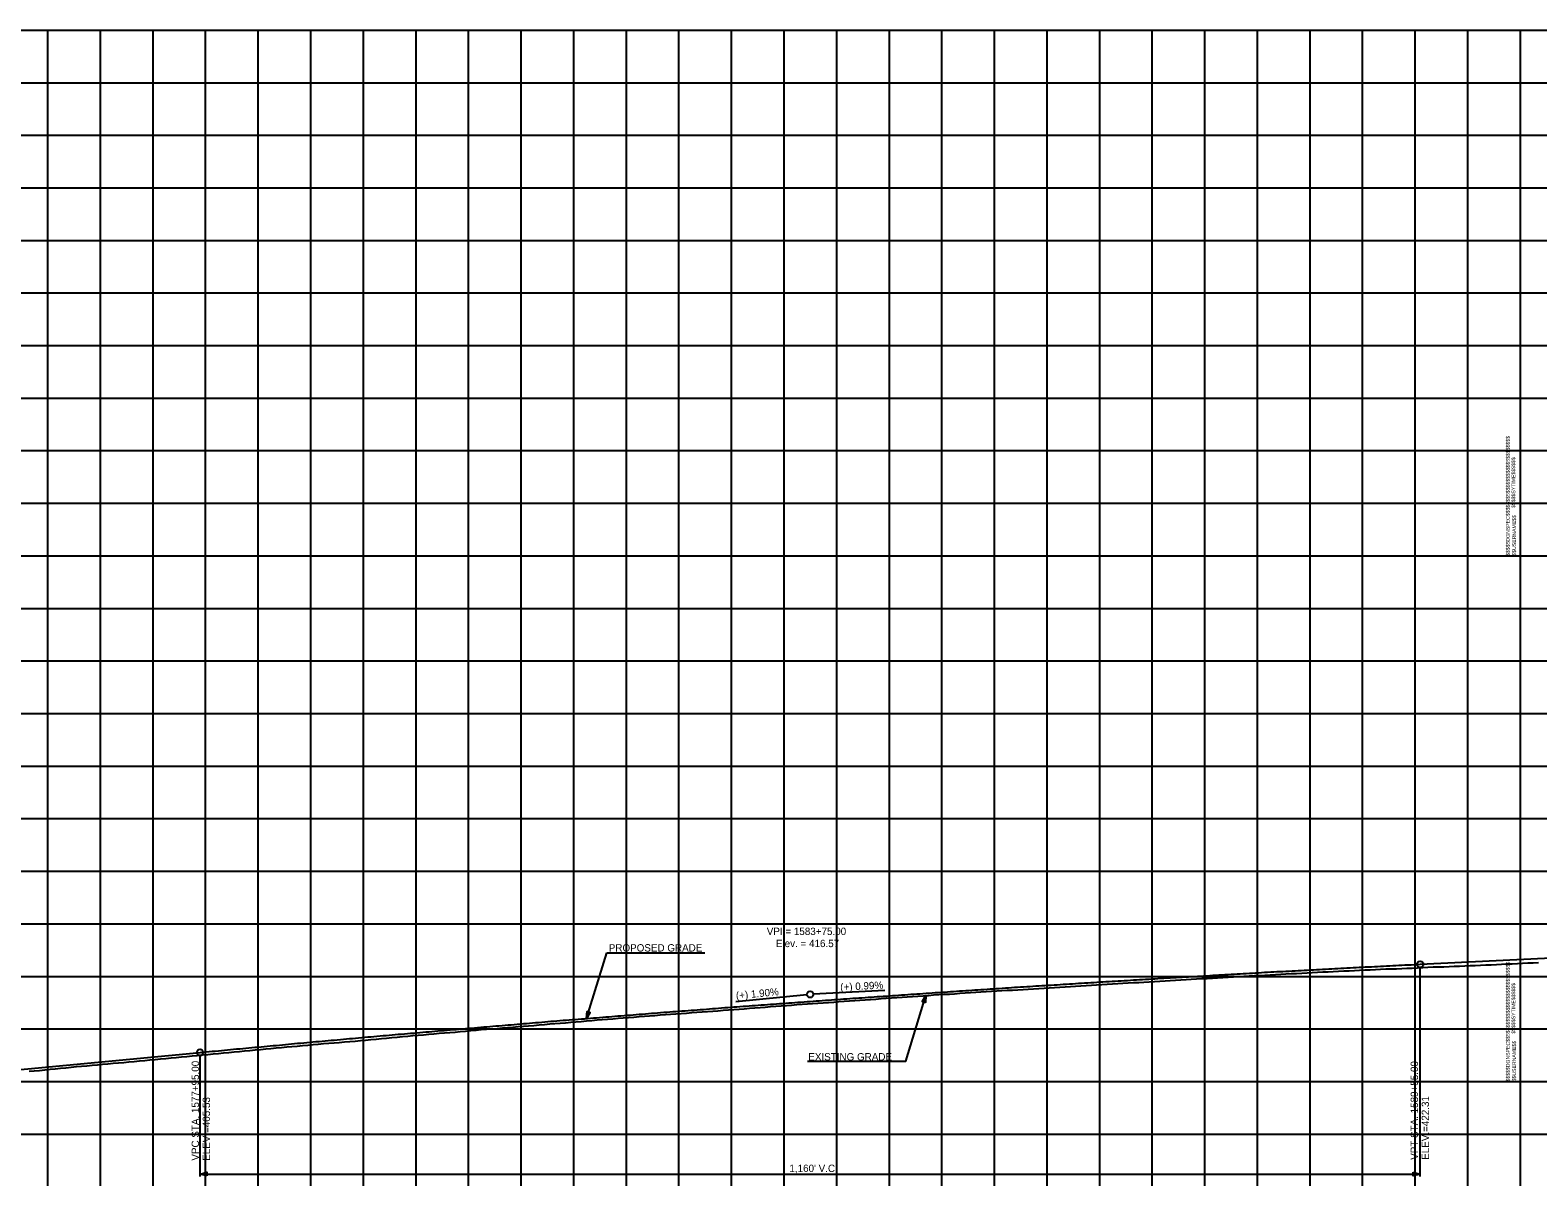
# Model space of a CAD drawing. Extents: x -90830 to 2015517, y -20856 to 836331.
# Drawn here: x 46557 to 47990, y -9888 to -8797 of the extents above; entities that cross this region are included whole.
import ezdxf

# ---------------------------------------------------------------- set-up
doc = ezdxf.new("R2010")
doc.units = 0
for name, color, linetype in [('Level 1', 7, 'Continuous'), ('RD_DDB_GradeTX', 7, 'Continuous'), ('RD_DDB_Profile_EX', 7, 'Continuous'), ('RD_DDB_Profile_Lbl', 7, 'Continuous'), ('RD_DDB_Profile_PR', 7, 'Continuous'), ('RD_DDB_StripGrade', 7, 'Continuous'), ('RD_DDB_VCLbl', 7, 'Continuous'), ('RD_PD_Final_TX', 7, 'Continuous')]:
    doc.layers.add(name, color=color, linetype=linetype)

msp = doc.modelspace()

# ---------------------------------------------------------------- linework, layer by layer
at = {"layer": 'Level 1'}
for p, q in [((46373.5, -8797.1), (47973.5, -8797.1)), ((46573.5, -8797.1), (46573.5, -9297.1)), ((46623.5, -8797.1), (46623.5, -9297.1)), ((46673.5, -8797.1), (46673.5, -9297.1)), ((46723.5, -8797.1), (46723.5, -9297.1)), ((46773.5, -8797.1), (46773.5, -9297.1)), ((46823.5, -8797.1), (46823.5, -9297.1)), ((46873.5, -8797.1), (46873.5, -9297.1)), ((46923.5, -8797.1), (46923.5, -9297.1)), ((46973.5, -8797.1), (46973.5, -9297.1)), ((47023.5, -8797.1), (47023.5, -9297.1)), ((47073.5, -8797.1), (47073.5, -9297.1)), ((47123.5, -8797.1), (47123.5, -9297.1)), ((47173.5, -8797.1), (47173.5, -9297.1)), ((47223.5, -8797.1), (47223.5, -9297.1)), ((47273.5, -8797.1), (47273.5, -9297.1)), ((47323.5, -8797.1), (47323.5, -9297.1)), ((47373.5, -8797.1), (47373.5, -9297.1)), ((47423.5, -8797.1), (47423.5, -9297.1)), ((47473.5, -8797.1), (47473.5, -9297.1)), ((47523.5, -8797.1), (47523.5, -9297.1)), ((47573.5, -8797.1), (47573.5, -9297.1)), ((47623.5, -8797.1), (47623.5, -9297.1)), ((47673.5, -8797.1), (47673.5, -9297.1)), ((47723.5, -8797.1), (47723.5, -9297.1)), ((47773.5, -8797.1), (47773.5, -9297.1)), ((47823.5, -8797.1), (47823.5, -9297.1)), ((47873.5, -8797.1), (47873.5, -9297.1)), ((47923.5, -8797.1), (47923.5, -9297.1)), ((47973.5, -8797.1), (47973.5, -9297.1)), ((47973.5, -8797.1), (47973.5, -9297.1)), ((47973.5, -8797.1), (49573.5, -8797.1)), ((47973.5, -8797.1), (47973.5, -9297.1)), ((46373.5, -8847.1), (47973.5, -8847.1)), ((47973.5, -8847.1), (49573.5, -8847.1)), ((46373.5, -8897.1), (47973.5, -8897.1)), ((47973.5, -8897.1), (49573.5, -8897.1)), ((46373.5, -8947.1), (47973.5, -8947.1)), ((47973.5, -8947.1), (49573.5, -8947.1)), ((46373.5, -8997.1), (47973.5, -8997.1)), ((47973.5, -8997.1), (49573.5, -8997.1)), ((46373.5, -9047.1), (47973.5, -9047.1)), ((47973.5, -9047.1), (49573.5, -9047.1)), ((46373.5, -9097.1), (47973.5, -9097.1)), ((47973.5, -9097.1), (49573.5, -9097.1)), ((46373.5, -9147.1), (47973.5, -9147.1)), ((47973.5, -9147.1), (49573.5, -9147.1)), ((46373.5, -9197.1), (47973.5, -9197.1)), ((47973.5, -9197.1), (49573.5, -9197.1)), ((46373.5, -9247.1), (47973.5, -9247.1)), ((47973.5, -9247.1), (49573.5, -9247.1)), ((46373.5, -9297.1), (47973.5, -9297.1)), ((46373.5, -9297.1), (47973.5, -9297.1)), ((46573.5, -9297.1), (46573.5, -9797.1)), ((46623.5, -9297.1), (46623.5, -9797.1)), ((46673.5, -9297.1), (46673.5, -9797.1)), ((46723.5, -9297.1), (46723.5, -9797.1)), ((46773.5, -9297.1), (46773.5, -9797.1)), ((46823.5, -9297.1), (46823.5, -9797.1)), ((46873.5, -9297.1), (46873.5, -9797.1)), ((46923.5, -9297.1), (46923.5, -9797.1)), ((46973.5, -9297.1), (46973.5, -9797.1)), ((47023.5, -9297.1), (47023.5, -9797.1)), ((47073.5, -9297.1), (47073.5, -9797.1)), ((47123.5, -9297.1), (47123.5, -9797.1)), ((47173.5, -9297.1), (47173.5, -9797.1)), ((47223.5, -9297.1), (47223.5, -9797.1)), ((47273.5, -9297.1), (47273.5, -9797.1)), ((47323.5, -9297.1), (47323.5, -9797.1)), ((47373.5, -9297.1), (47373.5, -9797.1)), ((47423.5, -9297.1), (47423.5, -9797.1)), ((47473.5, -9297.1), (47473.5, -9797.1)), ((47523.5, -9297.1), (47523.5, -9797.1)), ((47573.5, -9297.1), (47573.5, -9797.1)), ((47623.5, -9297.1), (47623.5, -9797.1)), ((47673.5, -9297.1), (47673.5, -9797.1)), ((47723.5, -9297.1), (47723.5, -9797.1)), ((47773.5, -9297.1), (47773.5, -9797.1)), ((47823.5, -9297.1), (47823.5, -9797.1)), ((47873.5, -9297.1), (47873.5, -9797.1)), ((47923.5, -9297.1), (47923.5, -9797.1)), ((47973.5, -9297.1), (47973.5, -9797.1)), ((47973.5, -9297.1), (47973.5, -9797.1)), ((47973.5, -9297.1), (49573.5, -9297.1)), ((47973.5, -9297.1), (47973.5, -9797.1)), ((47973.5, -9297.1), (49573.5, -9297.1)), ((46373.5, -9347.1), (47973.5, -9347.1)), ((47973.5, -9347.1), (49573.5, -9347.1)), ((46373.5, -9397.1), (47973.5, -9397.1)), ((47973.5, -9397.1), (49573.5, -9397.1)), ((46373.5, -9447.1), (47973.5, -9447.1)), ((47973.5, -9447.1), (49573.5, -9447.1)), ((46373.5, -9497.1), (47973.5, -9497.1)), ((47973.5, -9497.1), (49573.5, -9497.1)), ((46373.5, -9547.1), (47973.5, -9547.1)), ((47973.5, -9547.1), (49573.5, -9547.1)), ((46373.5, -9597.1), (47973.5, -9597.1)), ((47973.5, -9597.1), (49573.5, -9597.1)), ((46373.5, -9647.1), (47973.5, -9647.1)), ((47973.5, -9647.1), (49573.5, -9647.1)), ((46373.5, -9697.1), (47973.5, -9697.1)), ((47973.5, -9697.1), (49573.5, -9697.1)), ((46373.5, -9747.1), (47973.5, -9747.1)), ((47973.5, -9747.1), (49573.5, -9747.1)), ((46373.5, -9797.1), (47973.5, -9797.1)), ((46373.5, -9797.1), (47973.5, -9797.1)), ((46573.5, -9797.1), (46573.5, -10297.1)), ((46623.5, -9797.1), (46623.5, -10297.1)), ((46673.5, -9797.1), (46673.5, -10297.1)), ((46723.5, -9797.1), (46723.5, -10297.1)), ((46773.5, -9797.1), (46773.5, -10297.1)), ((46823.5, -9797.1), (46823.5, -10297.1)), ((46873.5, -9797.1), (46873.5, -10297.1)), ((46923.5, -9797.1), (46923.5, -10297.1)), ((46973.5, -9797.1), (46973.5, -10297.1)), ((47023.5, -9797.1), (47023.5, -10297.1)), ((47073.5, -9797.1), (47073.5, -10297.1)), ((47123.5, -9797.1), (47123.5, -10297.1)), ((47173.5, -9797.1), (47173.5, -10297.1)), ((47223.5, -9797.1), (47223.5, -10297.1)), ((47273.5, -9797.1), (47273.5, -10297.1)), ((47323.5, -9797.1), (47323.5, -10297.1)), ((47373.5, -9797.1), (47373.5, -10297.1)), ((47423.5, -9797.1), (47423.5, -10297.1)), ((47473.5, -9797.1), (47473.5, -10297.1)), ((47523.5, -9797.1), (47523.5, -10297.1)), ((47573.5, -9797.1), (47573.5, -10297.1)), ((47623.5, -9797.1), (47623.5, -10297.1)), ((47673.5, -9797.1), (47673.5, -10297.1)), ((47723.5, -9797.1), (47723.5, -10297.1)), ((47773.5, -9797.1), (47773.5, -10297.1)), ((47823.5, -9797.1), (47823.5, -10297.1)), ((47873.5, -9797.1), (47873.5, -10297.1)), ((47923.5, -9797.1), (47923.5, -10297.1)), ((47973.5, -9797.1), (47973.5, -10297.1)), ((47973.5, -9797.1), (47973.5, -10297.1)), ((47973.5, -9797.1), (49573.5, -9797.1)), ((47973.5, -9797.1), (47973.5, -10297.1)), ((47973.5, -9797.1), (49573.5, -9797.1)), ((46373.5, -9847.1), (47973.5, -9847.1)), ((47973.5, -9847.1), (49573.5, -9847.1))]:
    msp.add_line(p, q, dxfattribs=at)
at = {"layer": 'RD_DDB_GradeTX'}
for p, q in [((47227.8, -9721), (47295.5, -9714.5)), ((47369.4, -9710.7), (47301.5, -9714.1))]:
    msp.add_line(p, q, dxfattribs=at)
msp.add_circle((47298.5, -9714.3), 3, dxfattribs=at)
at = {"layer": 'RD_DDB_Profile_EX'}
for points in [[(47420.9, -9714.5), (47425.9, -9714.2), (47430.9, -9713.9), (47435.9, -9713.6), (47440.9, -9713.2), (47445.9, -9712.9), (47450.9, -9712.6), (47455.9, -9712.3), (47460.9, -9711.9), (47465.9, -9711.6), (47470.9, -9711.3), (47475.9, -9711), (47480.9, -9710.6), (47485.9, -9710.4), (47490.9, -9710.1), (47495.9, -9709.8), (47500.9, -9709.5), (47505.9, -9709.2), (47510.9, -9708.9), (47515.9, -9708.6), (47520.9, -9708.3), (47525.9, -9708), (47530.9, -9707.6), (47535.9, -9707.3), (47540.9, -9707), (47545.9, -9706.7), (47550.9, -9706.4), (47555.9, -9706.1), (47560.9, -9705.8), (47565.9, -9705.5), (47570.9, -9705.2), (47575.9, -9704.9), (47580.9, -9704.6), (47585.9, -9704.3), (47590.9, -9704), (47595.9, -9703.7), (47600.9, -9703.4), (47605.9, -9703.1), (47610.9, -9702.8), (47615.9, -9702.5), (47620.9, -9702.2), (47625.9, -9701.9), (47630.9, -9701.6), (47635.9, -9701.3), (47640.9, -9701), (47645.9, -9700.7), (47650.9, -9700.4), (47655.9, -9700.2), (47660.9, -9699.9), (47665.9, -9699.6), (47670.9, -9699.3), (47675.9, -9699), (47680.9, -9698.7), (47685.9, -9698.4), (47690.9, -9698.1), (47695.9, -9697.8), (47700.9, -9697.6), (47705.9, -9697.3), (47710.9, -9697), (47715.9, -9696.7), (47720.9, -9696.4), (47725.9, -9696.2), (47730.9, -9695.9), (47735.9, -9695.6), (47740.9, -9695.3), (47745.9, -9695.1), (47750.9, -9694.8), (47755.9, -9694.5), (47760.9, -9694.3), (47765.9, -9694), (47770.9, -9693.7), (47775.9, -9693.4), (47780.9, -9693.2), (47785.9, -9692.9), (47790.9, -9692.7), (47795.9, -9692.4), (47800.9, -9692.2), (47805.9, -9692), (47810.9, -9691.7), (47815.9, -9691.5), (47820.9, -9691.2), (47825.9, -9691), (47830.9, -9690.8), (47835.9, -9690.5), (47840.9, -9690.3), (47845.9, -9690.1), (47850.9, -9690), (47855.9, -9689.8), (47860.9, -9689.7), (47865.9, -9689.4), (47870.9, -9689.2), (47875.9, -9688.9), (47880.9, -9688.7), (47885.9, -9688.4), (47890.9, -9688.2), (47895.9, -9688), (47900.9, -9687.9), (47905.9, -9687.7), (47910.9, -9687.5), (47915.9, -9687.3), (47920.9, -9687.2)], [(47920.9, -9687.2), (47925.9, -9686.9), (47930.9, -9686.7), (47935.9, -9686.4), (47940.9, -9686.2), (47945.9, -9686), (47950.9, -9685.8), (47955.9, -9685.5), (47960.9, -9685.3), (47965.9, -9685.1), (47970.9, -9684.9), (47975.9, -9684.6), (47980.9, -9684.4), (47985.9, -9684.1), (47990.9, -9683.9)], [(46920.9, -9753.5), (46925.9, -9753.1), (46930.9, -9752.7), (46935.9, -9752.2), (46940.9, -9751.8), (46945.9, -9751.3), (46950.9, -9750.9), (46955.9, -9750.5), (46960.9, -9750.1), (46965.9, -9749.6), (46970.9, -9749.2), (46975.9, -9748.7), (46980.9, -9748.3), (46985.9, -9747.8), (46990.9, -9747.4), (46995.9, -9747), (47000.9, -9746.6), (47005.9, -9746.1), (47010.9, -9745.7), (47015.9, -9745.3), (47020.9, -9744.9), (47025.9, -9744.5), (47030.9, -9744.1), (47035.9, -9743.7), (47040.9, -9743.3), (47045.9, -9742.9), (47050.9, -9742.4), (47055.9, -9742), (47060.9, -9741.6), (47065.9, -9741.2), (47070.9, -9740.8), (47075.9, -9740.3), (47080.9, -9739.9), (47085.9, -9739.5), (47090.9, -9739), (47095.9, -9738.6), (47100.9, -9738.2), (47105.9, -9737.8), (47110.9, -9737.4), (47115.9, -9737), (47120.9, -9736.6), (47125.9, -9736.2), (47130.9, -9735.8), (47135.9, -9735.4), (47140.9, -9735), (47145.9, -9734.6), (47150.9, -9734.2), (47155.9, -9733.8), (47160.9, -9733.5), (47165.9, -9733.1), (47170.9, -9732.7), (47175.9, -9732.3), (47180.9, -9732), (47185.9, -9731.6), (47190.9, -9731.2), (47195.9, -9730.9), (47200.9, -9730.5), (47205.9, -9730.1), (47210.9, -9729.8), (47215.9, -9729.4), (47220.9, -9729), (47225.9, -9728.7), (47230.9, -9728.3), (47235.9, -9727.9), (47240.9, -9727.5), (47245.9, -9727.1), (47250.9, -9726.7), (47255.9, -9726.3), (47260.9, -9725.9), (47265.9, -9725.5), (47270.9, -9725.1), (47275.9, -9724.8), (47280.9, -9724.4), (47285.9, -9724), (47290.9, -9723.7), (47295.9, -9723.3), (47300.9, -9722.9), (47305.9, -9722.6), (47310.9, -9722.2), (47315.9, -9721.9), (47320.9, -9721.5), (47325.9, -9721.1), (47330.9, -9720.8), (47335.9, -9720.4), (47340.9, -9720), (47345.9, -9719.7), (47350.9, -9719.3), (47355.9, -9719), (47360.9, -9718.7), (47365.9, -9718.3), (47370.9, -9717.9), (47375.9, -9717.6), (47380.9, -9717.2), (47385.9, -9716.9), (47390.9, -9716.5), (47395.9, -9716.2), (47400.9, -9715.9), (47405.9, -9715.5), (47410.9, -9715.2), (47415.9, -9714.8), (47420.9, -9714.5)], [(46555.9, -9787.4), (46560.9, -9786.9), (46565.9, -9786.5), (46570.9, -9786), (46575.9, -9785.5), (46580.9, -9785), (46585.9, -9784.5), (46590.9, -9784), (46595.9, -9783.5), (46600.9, -9783), (46605.9, -9782.5), (46610.9, -9782.1), (46615.9, -9781.6), (46620.9, -9781.2), (46625.9, -9780.7), (46630.9, -9780.3), (46635.9, -9779.8), (46640.9, -9779.3), (46645.9, -9778.9), (46650.9, -9778.4), (46655.9, -9778), (46660.9, -9777.5), (46665.9, -9777.1), (46670.9, -9776.6), (46675.9, -9776.1), (46680.9, -9775.7), (46685.9, -9775.2), (46690.9, -9774.7), (46695.9, -9774.2), (46700.9, -9773.7), (46705.9, -9773.2), (46710.9, -9772.8), (46715.9, -9772.3), (46720.9, -9771.8), (46725.9, -9771.3), (46730.9, -9770.9), (46735.9, -9770.4), (46740.9, -9770), (46745.9, -9769.5), (46750.9, -9769), (46755.9, -9768.5), (46760.9, -9768), (46765.9, -9767.6), (46770.9, -9767.1), (46775.9, -9766.6), (46780.9, -9766.1), (46785.9, -9765.7), (46790.9, -9765.2), (46795.9, -9764.8), (46800.9, -9764.3), (46805.9, -9763.9), (46810.9, -9763.4), (46815.9, -9762.9), (46820.9, -9762.5), (46825.9, -9762), (46830.9, -9761.6), (46835.9, -9761.1), (46840.9, -9760.7), (46845.9, -9760.3), (46850.9, -9759.9), (46855.9, -9759.5), (46860.9, -9759.1), (46865.9, -9758.6), (46870.9, -9758.2), (46875.9, -9757.7), (46880.9, -9757.3), (46885.9, -9756.8), (46890.9, -9756.3), (46895.9, -9755.8), (46900.9, -9755.4), (46905.9, -9754.9), (46910.9, -9754.4), (46915.9, -9754), (46920.9, -9753.5)]]:
    msp.add_lwpolyline(points, dxfattribs=at)
at = {"layer": 'RD_DDB_Profile_PR'}
for p, q in [((47878.5, -9685.6), (48023.5, -9678.4)), ((46448.5, -9795.2), (46718.5, -9769.5))]:
    msp.add_line(p, q, dxfattribs=at)
msp.add_spline([(46718.5, -9769.5), (46741.7, -9767.3), (46764.9, -9765.1), (46788.1, -9763), (46811.3, -9760.8), (46834.5, -9758.7), (46857.7, -9756.6), (46880.9, -9754.5), (46904.1, -9752.5), (46927.3, -9750.5), (46950.5, -9748.5), (46973.7, -9746.5), (46996.9, -9744.5), (47020.1, -9742.6), (47043.3, -9740.6), (47066.5, -9738.7), (47089.7, -9736.9), (47112.9, -9735), (47136.1, -9733.2), (47159.3, -9731.3), (47182.5, -9729.6), (47205.7, -9727.8), (47228.9, -9726), (47252.1, -9724.3), (47275.3, -9722.6), (47298.5, -9720.9), (47321.7, -9719.2), (47344.9, -9717.6), (47368.1, -9716), (47391.3, -9714.4), (47414.5, -9712.8), (47437.7, -9711.2), (47460.9, -9709.7), (47484.1, -9708.1), (47507.3, -9706.6), (47530.5, -9705.2), (47553.7, -9703.7), (47576.9, -9702.3), (47600.1, -9700.9), (47623.3, -9699.5), (47646.5, -9698.1), (47669.7, -9696.8), (47692.9, -9695.4), (47716.1, -9694.1), (47739.3, -9692.8), (47762.5, -9691.6), (47785.7, -9690.3), (47808.9, -9689.1), (47832.1, -9687.9), (47855.3, -9686.7), (47878.5, -9685.6)], degree=3, dxfattribs=at)
at = {"layer": 'RD_DDB_VCLbl'}
for p, q in [((47878.5, -9887.6), (47878.5, -9688.6)), ((46718.5, -9887.6), (46718.5, -9772.5)), ((46718.5, -9885.1), (47878.5, -9885.1))]:
    msp.add_line(p, q, dxfattribs=at)
for centre in [(47878.5, -9685.6), (46718.5, -9769.5)]:
    msp.add_circle(centre, 3, dxfattribs=at)
at = {"layer": 'RD_PD_Final_TX'}
for p, q in [((47086, -9737.1), (47105.1, -9674.8)), ((47105.1, -9674.8), (47198.5, -9674.8)), ((47408.4, -9715.4), (47405, -9721.1)), ((47406.6, -9721.6), (47408.4, -9715.4)), ((47408.4, -9715.4), (47408.1, -9722)), ((47086, -9737.1), (47086.4, -9730.5)), ((47087.9, -9731), (47086, -9737.1)), ((47086, -9737.1), (47089.5, -9731.4)), ((47086.4, -9730.5), (47089.5, -9731.4)), ((47408.1, -9722), (47405, -9721.1))]:
    msp.add_line(p, q, dxfattribs=at)
for points in [[(47296, -9777.7), (47389.4, -9777.7), (47408.4, -9715.4)], [(47408.3, -9715.7), (47406.5, -9721.5), (47408.2, -9715.9), (47406.5, -9721.4), (47408.1, -9716.1), (47406.4, -9721.5), (47408, -9716.3), (47406.4, -9721.4), (47407.8, -9716.5), (47406.3, -9721.4), (47407.7, -9716.7), (47406.2, -9721.4), (47407.6, -9716.9), (47406.2, -9721.4), (47407.4, -9717.2), (47406.1, -9721.4), (47407.3, -9717.4), (47406, -9721.4), (47407.2, -9717.7), (47406, -9721.3), (47407, -9717.9), (47405.9, -9721.3), (47406.8, -9718.2), (47405.9, -9721.3), (47406.6, -9718.5), (47405.8, -9721.3), (47406.5, -9718.7), (47405.7, -9721.3), (47406.3, -9719), (47405.7, -9721.2), (47406.2, -9719.3), (47405.6, -9721.2), (47406, -9719.6), (47405.5, -9721.1), (47405.8, -9719.8), (47405.5, -9721.1), (47405.7, -9720.1), (47405.4, -9721.1), (47405.6, -9720.3), (47405.3, -9721.1), (47405.4, -9720.5), (47405.2, -9721), (47405.1, -9721.1), (47405.2, -9721)], [(47406.6, -9721.5), (47408.4, -9715.7), (47406.7, -9721.5), (47408.4, -9716), (47406.7, -9721.5), (47408.4, -9716.2), (47406.8, -9721.5), (47408.4, -9716.4), (47406.9, -9721.6), (47408.3, -9716.8), (47407, -9721.6), (47408.3, -9717.2), (47407, -9721.6), (47408.3, -9717.5), (47407.1, -9721.7), (47408.3, -9717.8), (47407.2, -9721.6), (47408.2, -9718.1), (47407.2, -9721.7), (47408.2, -9718.3), (47407.3, -9721.7), (47408.2, -9718.7), (47407.4, -9721.7), (47408.2, -9719.1), (47407.5, -9721.8), (47408.2, -9719.4), (47407.5, -9721.8), (47408.2, -9719.9), (47407.6, -9721.8), (47408.1, -9720.3), (47407.7, -9721.9), (47408.1, -9720.6), (47407.8, -9721.9), (47408.1, -9720.9), (47407.8, -9721.9), (47408.1, -9721.2), (47407.9, -9721.9), (47408.1, -9721.6), (47408, -9721.9)], [(47087.9, -9731), (47086.1, -9736.8), (47087.8, -9731), (47086.1, -9736.5), (47087.8, -9731), (47086.1, -9736.3), (47087.7, -9731), (47086.1, -9736.1), (47087.6, -9730.9), (47086.2, -9735.7), (47087.5, -9730.9), (47086.2, -9735.3), (47087.5, -9730.9), (47086.2, -9735), (47087.4, -9730.9), (47086.2, -9734.7), (47087.3, -9730.9), (47086.3, -9734.4), (47087.3, -9730.8), (47086.3, -9734.2), (47087.2, -9730.8), (47086.3, -9733.8), (47087.1, -9730.8), (47086.3, -9733.4), (47087, -9730.7), (47086.3, -9733.1), (47087, -9730.7), (47086.3, -9732.6), (47086.9, -9730.7), (47086.4, -9732.3), (47086.8, -9730.6), (47086.4, -9731.9), (47086.7, -9730.6), (47086.4, -9731.6), (47086.7, -9730.6), (47086.4, -9731.3), (47086.6, -9730.6), (47086.4, -9730.9), (47086.5, -9730.6)], [(47086.2, -9736.8), (47088, -9731), (47086.3, -9736.6), (47088, -9731.1), (47086.4, -9736.4), (47088.1, -9731.1), (47086.5, -9736.2), (47088.1, -9731.1), (47086.7, -9736), (47088.2, -9731.1), (47086.8, -9735.8), (47088.3, -9731.1), (47086.9, -9735.6), (47088.3, -9731.1), (47087.1, -9735.3), (47088.4, -9731.2), (47087.2, -9735.1), (47088.5, -9731.1), (47087.3, -9734.8), (47088.5, -9731.2), (47087.5, -9734.6), (47088.6, -9731.2), (47087.7, -9734.4), (47088.6, -9731.3), (47087.9, -9734), (47088.7, -9731.2), (47088, -9733.8), (47088.8, -9731.2), (47088.2, -9733.5), (47088.8, -9731.3), (47088.3, -9733.2), (47088.9, -9731.3), (47088.5, -9733), (47089, -9731.4), (47088.7, -9732.7), (47089, -9731.4), (47088.8, -9732.4), (47089.1, -9731.4), (47088.9, -9732.2), (47089.2, -9731.4), (47089.1, -9732.1), (47089.3, -9731.5), (47089.4, -9731.5), (47089.3, -9731.5)]]:
    msp.add_lwpolyline(points, dxfattribs=at)
for points in [[(46725.1, -9886.8), (46718.5, -9885.1), (46725.1, -9883.5)], [(47871.9, -9883.5), (47878.5, -9885.1), (47871.9, -9886.8)]]:
    msp.add_lwpolyline(points, close=True, dxfattribs=at)

# ---------------------------------------------------------------- texts
at = {"layer": 'Level 1'}
for s, p in [('$$$$$DGNSPEC$$$$$$$$$$$$$$$$$$$$$$$$$$$$', (47963.6, -9297.2)), ('$$$$$SYTIME$$$$$$', (47968.9, -9251.6)), ('$$USERNAME$$', (47969.5, -9297)), ('$$$$$DGNSPEC$$$$$$$$$$$$$$$$$$$$$$$$$$$$', (47963.6, -9797.2)), ('$$$$$SYTIME$$$$$$', (47968.9, -9751.6)), ('$$USERNAME$$', (47969.5, -9797))]:
    msp.add_text(s, height=3.544, rotation=90, dxfattribs=at).set_placement(p)
at = {"layer": 'RD_DDB_GradeTX'}
for s, rotation, p in [('(+) 0.99%', 2.8305, (47327.3, -9710.8)), ('(+) 1.90%', 5.4402, (47228.3, -9718.9))]:
    msp.add_text(s, height=7, rotation=rotation, dxfattribs=at).set_placement(p)
at = {"layer": 'RD_DDB_Profile_Lbl'}
for s, p in [('VPI = 1583+75.00', (47257.3, -9657.8)), ('Elev. = 416.57', (47266, -9669.3))]:
    msp.add_text(s, height=7, dxfattribs=at).set_placement(p)
at = {"layer": 'RD_DDB_StripGrade'}
for s, p in [('VPC STA. 1577+95.00 ', (46717.5, -9872.4)), ('VPT STA. 1589+55.00 ', (47876.4, -9871.6)), ('ELEV.=405.53', (46728, -9872.6)), ('ELEV.=422.31', (47886.9, -9871.6))]:
    msp.add_text(s, height=7, rotation=90, dxfattribs=at).set_placement(p)
at = {"layer": 'RD_DDB_VCLbl'}
msp.add_text("1,160' V.C.", height=7, dxfattribs=at).set_placement((47278.8, -9883.2))
at = {"layer": 'RD_PD_Final_TX'}
for s, p in [('PROPOSED GRADE', (47107.1, -9673.5)), ('EXISTING GRADE', (47296.8, -9777.1))]:
    msp.add_text(s, height=7, dxfattribs=at).set_placement(p)

doc.saveas('drawing.dxf')
